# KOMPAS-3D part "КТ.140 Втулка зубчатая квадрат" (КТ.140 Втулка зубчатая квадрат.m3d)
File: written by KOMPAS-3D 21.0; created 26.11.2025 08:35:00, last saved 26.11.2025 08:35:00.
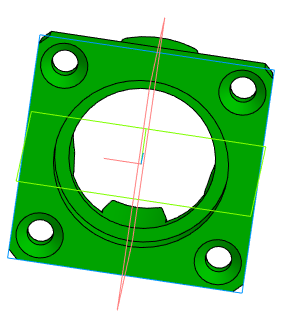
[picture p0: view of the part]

Document properties: Автор: User; Организация: User; Полное имя файла: C:\Users\User\Desktop\Pelorus PRO доработки\ЗАФИКСИРОВАЛИ\Втулка зубчатая квадрат\КТ.140 Втулка зубчатая квадрат.m3d

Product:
- Part/product: КТ.140 Втулка зубчатая квадрат
    Масса: 0.101259
    Комментарий: User

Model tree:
1. Операция без истории:1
